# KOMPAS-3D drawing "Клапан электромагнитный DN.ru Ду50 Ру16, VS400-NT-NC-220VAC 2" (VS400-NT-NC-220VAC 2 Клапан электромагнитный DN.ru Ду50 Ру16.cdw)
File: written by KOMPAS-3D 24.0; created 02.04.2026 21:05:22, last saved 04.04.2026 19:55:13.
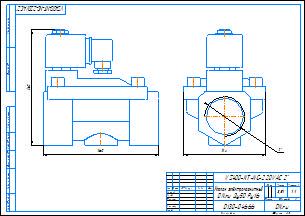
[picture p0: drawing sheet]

Document properties: c3d_UniqueCompID: ef56311e-7521-43dc-8291-0e6108b3d81d; Обозначение: VS400-ET-NC-220VAC 2; Наименование: Клапан электромагнитный DN.ru Ду50 Ру16; Автор: artio; Класс точности: c; Знак неуказанной шероховатости: Шероховатость не задана; Рассекать на разрезах: Да; c3d_UniqueCompID: ef56311e-7521-43dc-8291-0e6108b3d81d; Обозначение: VS400-ET-NC-220VAC 1; Наименование: Клапан электромагнитный DN.ru Ду25 Ру16; Автор: artio; Класс точности: c; Знак неуказанной шероховатости: Шероховатость не задана; Рассекать на разрезах: Да; c3d_UniqueCompID: ef56311e-7521-43dc-8291-0e6108b3d81d; Обозначение: VS400-ET-NC-220VAC 1-2; Наименование: Клапан электромагнитный DN.ru Ду15 Ру16; Автор: artio; Класс точности: c; Знак неуказанной шероховатости: Шероховатость не задана; Рассекать на разрезах: Да; c3d_UniqueCompID: ef56311e-7521-43dc-8291-0e6108b3d81d; Обозначение: VS400-ET-NC-220VAC 3-4; Наименование: Клапан электромагнитный DN.ru Ду20 Ру16; Автор: artio; Класс точности: c; Знак неуказанной шероховатости: Шероховатость не задана; Рассекать на разрезах: Да; c3d_UniqueCompID: ef56311e-7521-43dc-8291-0e6108b3d81d; Обозначение: VS400-ET-NC-220VAC 1 1-4; Наименование: Клапан электромагнитный DN.ru Ду32 Ру16; Автор: artio; Класс точности: c; Знак неуказанной шероховатости: Шероховатость не задана; Рассекать на разрезах: Да; c3d_UniqueCompID: ef56311e-7521-43dc-8291-0e6108b3d81d; Обозначение: VS400-ET-NC-220VAC 3-8; Наименование: Клапан электромагнитный DN.ru Ду10 Ру16; Автор: artio; Класс точности: c; Знак неуказанной шероховатости: Шероховатость не задана; Рассекать на разрезах: Да; c3d_UniqueCompID: ef56311e-7521-43dc-8291-0e6108b3d81d; Обозначение: VS400-ET-NC-220VAC 1 1-2; Наименование: Клапан электромагнитный DN.ru Ду40 Ру16; Автор: artio; Класс точности: c; Знак неуказанной шероховатости: Шероховатость не задана; Рассекать на разрезах: Да; Автор: artio; Форматы листов документа: A3; Полное имя файла: VS400-NT-NC-220VAC 2 Клапан электромагнитный DN.ru Ду50 Ру16.m3d; Масса: 3.509; Наименование: Клапан электромагнитный DN.ru Ду50 Ру16; Количество листов документа: 1; Примечание: D130-04666

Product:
- Body: Тело 1  | qty 1
    Масса: 7.119215
- Part/product: Клапан электромагнитный DN.ru Ду50 Ру16  | designation VS400-NT-NC-220VAC 2
    Масса: 3.509
    Раздел спецификации: Прочие изделия
    Примечание: D130-04666
    additional columns: ef56311e-7521-43dc-8291-0e6108b3d81d; VS400-ET-NC-220VAC 2; artio; c; Шероховатость не задана; Да

Views: Вид 1, Спереди
Referenced files in C:\Users\artio\OneDrive\Рабочий стол\Клапан электромагнитный DN.ru VS4x-xT-NC-x\DN10\: VS400-ET-NC-220VAC 3-8 Клапан электромагнитный DN.ru Ду10 Ру16.m3d, VS400-ET-NC-220VAC 3-8 Клапан электромагнитный DN.ru Ду10 Ру16.cdw
Referenced files in C:\Users\artio\OneDrive\Рабочий стол\Клапан электромагнитный DN.ru\VS400-NT-NC\VS400-NT-NC-220VAC\: VS400-NT-NC-220VAC 2 Клапан электромагнитный DN.ru Ду50 Ру16.m3d
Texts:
  VS400-NT-NC-220VAC 2
  Клапан электромагнитный
  DN.ru Ду50 Ру16
  VS400-NT-NC-220VAC 2"
  VS400-NT-NC-220VAC 2"-
  Клапан электромагнитный DN.ru Ду50 Ру16
  VS400-NT-NC-220VAC 2 Клапан электромагнитный DN.ru Ду50 Ру16
Dimensions and other numbers on the sheet: 0; 3; 2; 4; 114; 1:1; 1; 3,51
